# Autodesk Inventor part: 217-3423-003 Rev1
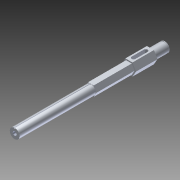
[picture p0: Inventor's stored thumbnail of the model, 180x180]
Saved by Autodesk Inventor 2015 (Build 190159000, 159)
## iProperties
Created: 2014-11
Part Number: 217-3423-003 Rev1
Material: Generic
Document SubType Name: Modeling
Designer: User
Density: 1 g/cm^3
Appearance: Default
Author: User
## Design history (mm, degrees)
node "217-3423-003 Rev1.ipt1"
sketch "Sketch1"
  geometry: L1 (4.583, 0)-(-2.75, 0) reference; L2 (0.917, 0)-(0.917, -6.35); L3 (0.123, -0.05)-(0.123, -0.794); L4 (0.123, -0.794)-(1.71, -0.794); L5 (1.71, -0.794)-(1.71, -0.05); L6 (1.833, 0)-(0, 0) reference; C1 r 10.929 at (0.917, -6.35); A1 r 6.35 centre (0.917, -6.35) between (0.123, -0.05) and (1.71, -0.05); 3 further points
  constraints: 8 end point, 3 midpoint, 2 centre point, 2 coincident, 2 perpendicular, 2 point on circle, 2 vertical, 1 point on line, 1 vertical alignment
  dimensions: "d0" = 12.7 diameter of A1; "d1" = 21.85716 diameter of C1; "d4" = 1.5875 distance of L3.end L4.end; "d5" = 0.79375 distance of L2.start point (0.917, -0.794)
extrude "Extrusion2" cut sketch "Sketch1" distance "d6" = 98.425; taper "d7" = 0 deg
node "1_4-20 Tapped Hole1"
node "Base1"
